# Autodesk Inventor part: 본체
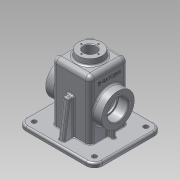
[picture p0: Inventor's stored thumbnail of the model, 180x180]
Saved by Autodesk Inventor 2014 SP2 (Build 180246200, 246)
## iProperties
Created: 2016-08
Part Number: 본체
Material: 알루미늄 6061
Document SubType Name: Modeling
Designer: user
Density: 2.71 g/cm^3
Appearance: 알루미늄 - 평지
Author: user
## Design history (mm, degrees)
sketch "스케치4"
  geometry: L1 (-65, 57.5)-(65, 57.5); L2 (65, 57.5)-(65, -57.5); L3 (65, -57.5)-(-65, -57.5); L4 (-65, -57.5)-(-65, 57.5); L5 (-65, 57.5)-(65, -57.5); L6 (65, 57.5)-(-65, -57.5); 1 further point
  constraints: 12 end point, 2 midpoint, 2 parallel, 1 horizontal, 1 perpendicular
  dimensions: "d11" = 130 distance of L1.start L1.end; "d12" = 115 distance of L1.end L2.end
extrude "돌출3" new body sketch "스케치4" distance "d13" = 10; taper "d14" = 0 deg
sketch "스케치5"
  geometry: L1 (-32.5, -32.5)-(32.5, -32.5); L2 (32.5, -32.5)-(32.5, 32.5); L3 (32.5, 32.5)-(-32.5, 32.5); L4 (-32.5, 32.5)-(-32.5, -32.5); L5 (-32.5, -32.5)-(32.5, 32.5); L6 (32.5, -32.5)-(-32.5, 32.5); 1 further point
  constraints: 12 end point, 2 midpoint, 2 parallel, 1 horizontal, 1 perpendicular
  dimensions: "d15" = 65 distance of L3.end L2.end; "d16" = 65 distance of L2.end L1.end
extrude "돌출4" join sketch "스케치5" distance "d17" = 100; taper "d18" = 0 deg
sketch "스케치6"
  geometry: L1 (0, 110)-(0, 120); L2 (0, 120)-(-20, 120); L3 (-20, 120)-(-21.228, 110); L4 (-32.5, 110)-(32.5, 110) reference; L5 (65, 0)-(-65, 0) reference; 1 further point
  constraints: 6 end point, 1 midpoint, 1 perpendicular, 1 point on line, 1 vertical
  dimensions: "d19" = 20 distance of L1.end L2.end; "d20" = 97 deg angle of L4 L3; "d21" = 120 distance between parallel lines of L5 L2
revolve "회전1" sketch "스케치6" stored, may be unused: angle "d22" = 90 deg
sketch "스케치7"
  geometry: C1 r 27.5 at (0, 55); 1 further point
  constraints: 1 centre point, 1 vertical alignment
  dimensions: "d23" = 55 diameter of C1; "d24" = 55 distance of point (0, 0) C1.centre
extrude "돌출5" join sketch "스케치7" stored distance "d25" = 95; taper "d26" = 0 deg
sketch "스케치8"
  geometry: L1 (27.5, -27.5)-(-27.5, -27.5); L2 (-27.5, -27.5)-(-27.5, 27.5); L3 (-27.5, 27.5)-(27.5, 27.5); L4 (27.5, 27.5)-(27.5, -27.5); L5 (27.5, -27.5)-(-27.5, 27.5); L6 (-27.5, -27.5)-(27.5, 27.5); 1 further point
  constraints: 12 end point, 2 midpoint, 2 parallel, 1 horizontal, 1 perpendicular
  dimensions: "d27" = 55 distance of L2.end L3.end; "d28" = 55 distance of L1.end L2.end
extrude "돌출6" cut sketch "스케치8" distance "d29" = 105; taper "d30" = 0 deg
hole "구멍1" diameter "d33" = 21; stored, may be unused: countersink angle "d37" = 90 deg, drill point angle "d39" = 118 deg; dims "d31" = 10, "d32" = 10, "d34" = 6, "d35" = 4, "d36" = 2, "d38" = 8
hole "구멍2" diameter "d42" = 35; stored, may be unused: countersink angle "d46" = 90 deg, drill point angle "d48" = 0 deg; dims "d43" = 6, "d44" = 4, "d45" = 2, "d47" = 17, "d58" = 10, "d59" = 10
hole "구멍3" diameter "d51" = 35; stored, may be unused: countersink angle "d55" = 90 deg, drill point angle "d57" = 0 deg; dims "d52" = 6, "d53" = 4, "d54" = 2, "d56" = 17, "d60" = 10, "d61" = 10
hole "구멍4" diameter "d64" = 30; stored, may be unused: countersink angle "d68" = 90 deg, drill point angle "d70" = 118 deg; dims "d62" = 10, "d63" = 10, "d65" = 6, "d66" = 4, "d67" = 2, "d69" = 3
hole "구멍5" diameter "d73" = 30; stored, may be unused: countersink angle "d77" = 90 deg, drill point angle "d79" = 118 deg; dims "d71" = 10, "d72" = 10, "d74" = 6, "d75" = 4, "d76" = 2, "d78" = 3
sketch "스케치9"
  geometry: 5 further points
  constraints: 1 horizontal alignment, 1 vertical alignment
  dimensions: "d80" = 102 distance of point (51, 43.5) point (-51, 43.5); "d81" = 87 distance of point (51, -43.5) point (51, 43.5); "d82" = 87 distance of point (-51, -43.5) point (-51, 43.5); "d83" = 102 distance of point (51, -43.5) point (-51, -43.5); "d84" = 51 horizontal distance of point (-51, -43.5) point (0, 0) (= 0.5 x d83); "d85" = 43.5 vertical distance of point (-51, -43.5) point (0, 0) (= 0.5 x d82)
hole "구멍6" sketch "스케치9" at (-51, 43.5), (51, 43.5), (51, -43.5), (-51, -43.5) diameter "d86" = 8; stored, may be unused: countersink angle "d90" = 90 deg, drill point angle "d92" = 118 deg; dims "d87" = 6, "d88" = 4, "d89" = 2, "d91" = 3
sketch "스케치10"
  geometry: L1 (-65, -57.5)-(65, -57.5) reference; L2 (65, -57.5)-(65, 57.5) reference; L3 (-65, 57.5)-(-65, -57.5) reference; L4 (65, 57.5)-(-65, 57.5) reference; L5 (60, -52.5)-(-60, -52.5); L6 (-60, -52.5)-(-60, 52.5); L7 (-60, 52.5)-(60, 52.5); L8 (60, 52.5)-(60, -52.5); 1 further point
  constraints: 8 end point, 3 other
  dimensions: "d93" = 5 distance between parallel lines of L1 L5
extrude "돌출7" cut sketch "스케치10" distance "d94" = 3; taper "d95" = 0 deg
fillet "모깎기1" dims "d96" = 14
sketch "스케치11"
  geometry: L1 (-42.5, 3)-(-27.5, 3); L2 (-27.5, 3)-(-27.5, -3); L3 (-27.5, -3)-(-42.5, -3); L4 (-42.5, -3)-(-42.5, 3); L5 (-42.5, 3)-(-27.5, -3); L6 (-27.5, 3)-(-42.5, -3); L7 (27.5, 3)-(42.5, 3); L8 (42.5, 3)-(42.5, -3); L9 (42.5, -3)-(27.5, -3); L10 (27.5, -3)-(27.5, 3); L11 (27.5, 3)-(42.5, -3); L12 (42.5, 3)-(27.5, -3); L13 (-27.5, 27.5)-(-27.5, -27.5) reference; L14 (27.5, -27.5)-(27.5, 27.5) reference; 7 further points
  constraints: 24 end point, 10 midpoint, 4 parallel, 2 horizontal, 2 horizontal alignment, 2 perpendicular
  dimensions: "d97" = 15 distance of L2.end L3.end; "d98" = 6 distance of L1.end L2.end; "d99" = 15 distance of L8.end L9.end; "d100" = 6 distance of L7.end L8.end
extrude "돌출8" join sketch "스케치11" stored distance "d101" = 3; taper "d102" = 0 deg
sketch "스케치12"
  geometry: C1 r 17.5 at (0, 0) reference; 2 further points
  constraints: 1 horizontal alignment
  dimensions: "d103" = 21 distance of C1.centre point (-21, 0)
hole "구멍7" sketch "스케치12" at (-21, 0) diameter "d104" = 3.242; stored, may be unused: countersink angle "d108" = 90 deg, drill point angle "d110" = 118 deg; dims "d105" = 8, "d106" = 4, "d107" = 2, "d109" = 10
fillet "모깎기2" dims "d114" = 8
sketch "스케치13"
  geometry: L1 (-41.068, 70)-(-49.5, 10); L2 (-39.5, 0)-(-47.5, 0) reference; L3 (-57.5, 10)-(-43.5, 10) reference; L4 (-57.5, 3)-(-57.5, 10) reference; L5 (-41.068, 70)-(-32.5, 70); L6 (-32.5, 10)-(-32.5, 102) reference; L7 (43.5, 10)-(-43.5, 10) reference; 1 further point
  constraints: 4 end point, 2 point on line, 1 perpendicular
  dimensions: "d115" = 70 distance from line of L2 L1.start; "d116" = 98 deg angle of L3 L1; "d117" = 8 distance from line of L4 L1.end
feature "리브1" sketch "스케치13" dims "d118" = 1, "d119" = 10, "d120" = 0, "d121" = 0, "d122" = 1, "d123" = 1
fillet "모깎기3" dims "d124" = 0.3
sketch "스케치14"
  geometry: 2 further points
  constraints: 1 vertical alignment
  dimensions: "d125" = 14.5 distance of point (0, 0) point (0, 14.5)
hole "구멍8" sketch "스케치14" at (0, 14.5) diameter "d126" = 2.459; stored, may be unused: countersink angle "d130" = 90 deg, drill point angle "d132" = 118 deg; dims "d127" = 7, "d128" = 4, "d129" = 2, "d131" = 9
fillet "모깎기4" dims "d136" = 3
fillet "모깎기5" dims "d137" = 3
fillet "모깎기8" dims "d140" = 3
fillet "모깎기9" dims "d141" = 3
fillet "모깎기10" dims "d142" = 1
fillet "모깎기11" dims "d143" = 9
sketch "스케치15"
  geometry: L1 (0, -8)-(91, -8) reference; L2 (-18, 44.5)-(-18, 4.5) reference; 2 further points
  constraints: 1 other
  dimensions: "d144" = 32.5 distance from line of L1 point (8, 24.5); "d145" = 26 distance from line of point (8, 24.5) L2
feature "엠보싱1" sketch "스케치15" dims "d146" = 0.5, "d147" = 0
fillet "모깎기12" dims "d148" = 3
fillet "모깎기13" dims "d149" = 3
chamfer "모따기1" distance "d150" = 1; stored, may be unused: second distance "d151" = 2, angle "d152" = 45 deg
chamfer "모따기2" distance "d153" = 1; stored, may be unused: second distance "d154" = 2, angle "d155" = 45 deg
chamfer "모따기3" distance "d156" = 1; stored, may be unused: second distance "d157" = 2, angle "d158" = 45 deg
node "솔리드2"
pattern_circular "원형 패턴1" dims angle "d112" = 360 deg
mirror "대칭1"
mirror "대칭2"
pattern_circular "원형 패턴2" dims angle "d134" = 360 deg
